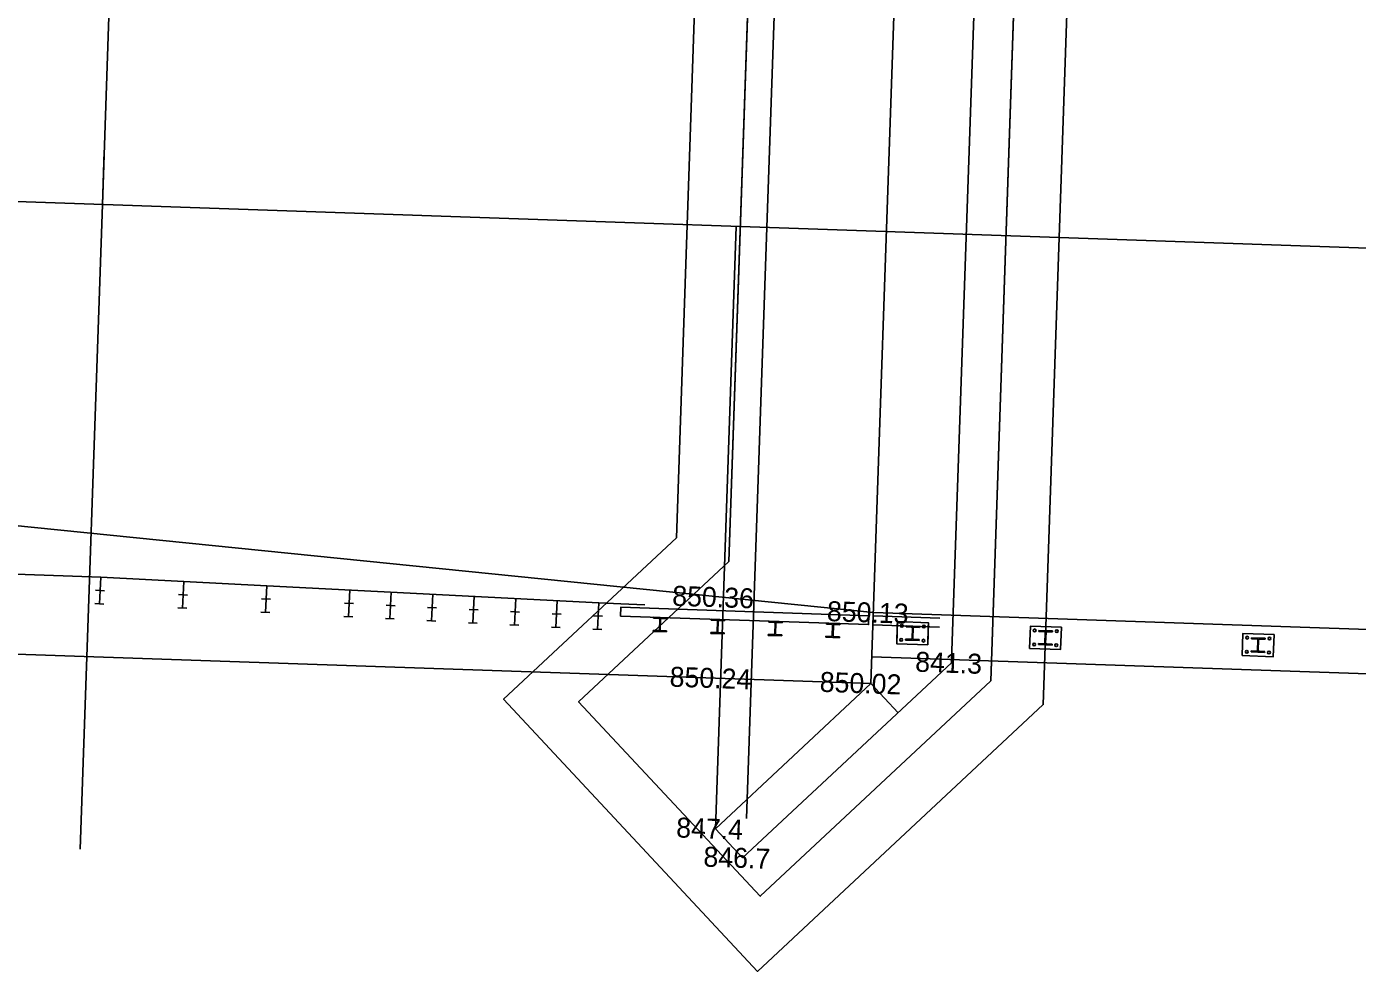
# Model space of a CAD drawing. Extents: x 2191309 to 2193046, y 863659 to 865133.
# Drawn here: x 2191665.3 to 2191715.3, y 865059 to 865094.6 of the extents above; entities that cross this region are included whole.
import ezdxf

# ---------------------------------------------------------------- set-up
doc = ezdxf.new("R2010")
doc.units = 0
for name, color, linetype in [('D_Bridge_Abutment', 7, 'Continuous'), ('D_Bridge_Deck', 7, 'Continuous'), ('D_Bridge_Railing', 7, 'Continuous'), ('D_Bridge_Substructure_Hidden', 7, 'Continuous'), ('D_Guardrail_Beam_Lt', 7, 'Continuous'), ('D_Guardrail_Beam_Rt', 7, 'Continuous'), ('D_Roadway_Centerline', 7, 'Continuous'), ('D_Roadway_Centerline_Text', 7, 'Continuous'), ('D_Roadway_Edge_Shoulder', 7, 'Continuous'), ('D_Roadway_Edge_TW', 7, 'Continuous'), ('H_V CONTROLS', 7, 'Continuous'), ('JUNK', 7, 'Continuous')]:
    doc.layers.add(name, color=color, linetype=linetype)

msp = doc.modelspace()

# ---------------------------------------------------------------- linework, layer by layer
at = {"layer": 'D_Bridge_Abutment'}
for p, q in [((2191697, 865069.864), (2191698.167, 865103.844)), ((2191700.044, 865071.093), (2191700.029, 865070.639)), ((2191700.029, 865070.639), (2191692.176, 865063.308)), ((2191697, 865069.864), (2191691.153, 865064.404)), ((2191698.024, 865068.767), (2191697, 865069.864)), ((2191692.176, 865063.308), (2191691.153, 865064.404))]:
    msp.add_line(p, q, dxfattribs=at)
at = {"layer": 'D_Bridge_Deck'}
for p, q in [((2191697.092, 865072.529), (2191734.07, 865071.26)), ((2191697.035, 865070.863), (2191734.013, 865069.594))]:
    msp.add_line(p, q, dxfattribs=at)
at = {"layer": 'D_Bridge_Railing'}
for p, q in [((2191688.826, 865072.316), (2191688.828, 865072.354)), ((2191689.036, 865072.309), (2191688.826, 865072.316)), ((2191688.828, 865072.354), (2191689.334, 865072.337)), ((2191689.052, 865071.882), (2191689.065, 865072.278)), ((2191689.092, 865072.277), (2191689.078, 865071.881)), ((2191689.333, 865072.299), (2191689.123, 865072.306)), ((2191689.334, 865072.337), (2191689.333, 865072.299)), ((2191690.992, 865072.242), (2191690.993, 865072.28)), ((2191691.202, 865072.235), (2191690.992, 865072.242)), ((2191690.993, 865072.28), (2191691.499, 865072.262)), ((2191691.217, 865071.808), (2191691.231, 865072.204)), ((2191691.257, 865072.203), (2191691.244, 865071.807)), ((2191691.498, 865072.225), (2191691.288, 865072.232)), ((2191691.499, 865072.262), (2191691.498, 865072.225)), ((2191693.157, 865072.168), (2191693.158, 865072.205)), ((2191693.367, 865072.16), (2191693.157, 865072.168)), ((2191693.158, 865072.205), (2191693.665, 865072.188)), ((2191693.663, 865072.15), (2191693.453, 865072.157)), ((2191693.665, 865072.188), (2191693.663, 865072.15)), ((2191688.809, 865071.823), (2191688.811, 865071.861)), ((2191689.316, 865071.805), (2191688.809, 865071.823)), ((2191688.811, 865071.861), (2191689.021, 865071.853)), ((2191689.107, 865071.85), (2191689.317, 865071.843)), ((2191689.317, 865071.843), (2191689.316, 865071.805)), ((2191690.975, 865071.748), (2191690.976, 865071.786)), ((2191691.481, 865071.731), (2191690.975, 865071.748)), ((2191690.976, 865071.786), (2191691.186, 865071.779)), ((2191691.272, 865071.776), (2191691.482, 865071.769)), ((2191691.482, 865071.769), (2191691.481, 865071.731)), ((2191693.14, 865071.674), (2191693.141, 865071.712)), ((2191693.647, 865071.657), (2191693.14, 865071.674)), ((2191693.141, 865071.712), (2191693.352, 865071.705)), ((2191693.382, 865071.734), (2191693.396, 865072.13)), ((2191693.423, 865072.129), (2191693.409, 865071.733)), ((2191693.438, 865071.702), (2191693.648, 865071.695)), ((2191693.648, 865071.695), (2191693.647, 865071.657)), ((2191695.323, 865072.093), (2191695.324, 865072.131)), ((2191695.533, 865072.086), (2191695.323, 865072.093)), ((2191695.324, 865072.131), (2191695.83, 865072.114)), ((2191695.548, 865071.659), (2191695.561, 865072.055)), ((2191695.588, 865072.054), (2191695.574, 865071.658)), ((2191695.829, 865072.076), (2191695.619, 865072.083)), ((2191695.83, 865072.114), (2191695.829, 865072.076)), ((2191698.319, 865071.992), (2191698.32, 865072.028)), ((2191698.53, 865071.985), (2191698.319, 865071.992)), ((2191698.32, 865072.028), (2191698.83, 865072.011)), ((2191698.321, 865071.99), (2191698.322, 865072.028)), ((2191698.531, 865071.983), (2191698.321, 865071.99)), ((2191698.322, 865072.028), (2191698.828, 865072.011)), ((2191698.546, 865071.556), (2191698.56, 865071.953)), ((2191698.546, 865071.556), (2191698.56, 865071.952)), ((2191698.586, 865071.952), (2191698.572, 865071.555)), ((2191698.586, 865071.951), (2191698.573, 865071.555)), ((2191698.827, 865071.973), (2191698.617, 865071.98)), ((2191698.829, 865071.974), (2191698.618, 865071.982)), ((2191698.828, 865072.011), (2191698.827, 865071.973)), ((2191698.83, 865072.011), (2191698.829, 865071.974)), ((2191703.316, 865071.82), (2191703.317, 865071.857)), ((2191703.527, 865071.813), (2191703.316, 865071.82)), ((2191703.317, 865071.857), (2191703.827, 865071.839)), ((2191703.543, 865071.385), (2191703.557, 865071.781)), ((2191703.583, 865071.78), (2191703.569, 865071.384)), ((2191703.826, 865071.803), (2191703.615, 865071.81)), ((2191703.827, 865071.839), (2191703.826, 865071.803)), ((2191695.306, 865071.6), (2191695.307, 865071.638)), ((2191695.812, 865071.582), (2191695.306, 865071.6)), ((2191695.307, 865071.638), (2191695.517, 865071.63)), ((2191695.603, 865071.628), (2191695.813, 865071.62)), ((2191695.813, 865071.62), (2191695.812, 865071.582)), ((2191698.302, 865071.497), (2191698.303, 865071.534)), ((2191698.812, 865071.48), (2191698.302, 865071.497)), ((2191698.303, 865071.534), (2191698.514, 865071.527)), ((2191698.304, 865071.497), (2191698.305, 865071.535)), ((2191698.81, 865071.48), (2191698.304, 865071.497)), ((2191698.305, 865071.535), (2191698.515, 865071.528)), ((2191698.601, 865071.525), (2191698.811, 865071.517)), ((2191698.602, 865071.524), (2191698.813, 865071.516)), ((2191698.811, 865071.517), (2191698.81, 865071.48)), ((2191698.813, 865071.516), (2191698.812, 865071.48)), ((2191703.299, 865071.326), (2191703.3, 865071.362)), ((2191703.809, 865071.308), (2191703.299, 865071.326)), ((2191703.3, 865071.362), (2191703.511, 865071.355)), ((2191703.599, 865071.352), (2191703.81, 865071.345)), ((2191703.81, 865071.345), (2191703.809, 865071.308)), ((2191711.311, 865071.546), (2191711.313, 865071.582)), ((2191711.522, 865071.539), (2191711.311, 865071.546)), ((2191711.313, 865071.582), (2191711.823, 865071.565)), ((2191711.539, 865071.11), (2191711.552, 865071.507)), ((2191711.578, 865071.506), (2191711.565, 865071.109)), ((2191711.821, 865071.528), (2191711.61, 865071.536)), ((2191711.823, 865071.565), (2191711.821, 865071.528)), ((2191711.294, 865071.051), (2191711.296, 865071.088)), ((2191711.804, 865071.034), (2191711.294, 865071.051)), ((2191711.296, 865071.088), (2191711.507, 865071.081)), ((2191711.594, 865071.078), (2191711.806, 865071.07)), ((2191711.806, 865071.07), (2191711.804, 865071.034))]:
    msp.add_line(p, q, dxfattribs=at)
for points in [[(2191687.582, 865072.397), (2191696.91, 865072.077), (2191696.921, 865072.41), (2191687.593, 865072.73), (2191687.582, 865072.397)], [(2191699.58, 865071.985), (2191697.076, 865072.071), (2191697.088, 865072.404), (2191699.592, 865072.318)], [(2191699.158, 865072), (2191699.163, 865072.15), (2191697.997, 865072.191), (2191697.992, 865072.04)], [(2191697.992, 865072.04), (2191697.969, 865071.358), (2191699.135, 865071.318), (2191699.158, 865072)]]:
    msp.add_lwpolyline(points, dxfattribs=at)
for points in [[(2191697.969, 865071.358), (2191699.135, 865071.318), (2191699.163, 865072.15), (2191697.997, 865072.191)], [(2191702.966, 865071.186), (2191704.132, 865071.146), (2191704.16, 865071.979), (2191702.994, 865072.019)], [(2191710.961, 865070.912), (2191712.127, 865070.872), (2191712.156, 865071.705), (2191710.99, 865071.745)]]:
    msp.add_lwpolyline(points, close=True, dxfattribs=at)
for centre in [(2191698.159, 865072.034), (2191698.992, 865072.005), (2191703.156, 865071.862), (2191703.989, 865071.834), (2191698.141, 865071.503), (2191698.141, 865071.503), (2191698.973, 865071.474), (2191698.973, 865071.474), (2191703.138, 865071.331), (2191703.97, 865071.303), (2191711.151, 865071.588), (2191711.984, 865071.559), (2191711.133, 865071.057), (2191711.966, 865071.028)]:
    msp.add_circle(centre, 0.0521, dxfattribs=at)
for centre, radius, start, end in [((2191689.035, 865072.279), 0.0298, 358.0343, 88.0343), ((2191689.122, 865072.276), 0.0298, 88.0343, 178.0343), ((2191691.201, 865072.205), 0.0298, 358.0343, 88.0343), ((2191691.287, 865072.202), 0.0298, 88.0343, 178.0343), ((2191693.366, 865072.131), 0.0298, 358.0343, 88.0343), ((2191693.452, 865072.128), 0.0298, 88.0343, 178.0343), ((2191689.022, 865071.883), 0.0298, 268.0343, 358.0343), ((2191689.108, 865071.88), 0.0298, 178.0343, 268.0343), ((2191691.187, 865071.809), 0.0298, 268.0343, 358.0343), ((2191691.273, 865071.806), 0.0298, 178.0343, 268.0343), ((2191693.353, 865071.735), 0.0298, 268.0343, 358.0343), ((2191693.439, 865071.732), 0.0298, 178.0343, 268.0343), ((2191695.518, 865071.66), 0.0298, 268.0343, 358.0343), ((2191695.532, 865072.056), 0.0298, 358.0343, 88.0343), ((2191695.604, 865071.657), 0.0298, 178.0343, 268.0343), ((2191695.618, 865072.053), 0.0298, 88.0343, 178.0343), ((2191698.529, 865071.954), 0.0308, 358.0343, 88.0343), ((2191698.53, 865071.953), 0.0298, 358.0343, 88.0343), ((2191698.617, 865071.951), 0.0308, 88.0343, 178.0343), ((2191698.616, 865071.95), 0.0298, 88.0343, 178.0343), ((2191703.526, 865071.782), 0.0308, 358.0343, 88.0343), ((2191703.614, 865071.779), 0.0308, 88.0343, 178.0343), ((2191698.515, 865071.557), 0.0308, 268.0343, 358.0343), ((2191698.516, 865071.557), 0.0298, 268.0343, 358.0343), ((2191698.603, 865071.554), 0.0308, 178.0343, 268.0343), ((2191698.602, 865071.554), 0.0298, 178.0343, 268.0343), ((2191703.513, 865071.386), 0.0308, 268.0343, 358.0343), ((2191703.6, 865071.383), 0.0308, 178.0343, 268.0343), ((2191711.521, 865071.508), 0.0308, 358.0343, 88.0343), ((2191711.609, 865071.505), 0.0308, 88.0343, 178.0343), ((2191711.508, 865071.111), 0.0308, 268.0343, 358.0343), ((2191711.595, 865071.108), 0.0308, 178.0343, 268.0343)]:
    msp.add_arc(centre, radius, start, end, dxfattribs=at)
at = {"layer": 'D_Bridge_Substructure_Hidden'}
for p, q in [((2191701.507, 865069.967), (2191702.655, 865103.432)), ((2191700.044, 865071.093), (2191701.131, 865102.741)), ((2191691.654, 865074.449), (2191692.519, 865099.636)), ((2191691.654, 865074.449), (2191686.01, 865069.18)), ((2191701.507, 865069.967), (2191692.835, 865061.87)), ((2191692.835, 865061.87), (2191686.01, 865069.18))]:
    msp.add_line(p, q, dxfattribs=at)
at = {"layer": 'D_Guardrail_Beam_Lt'}
for p, q in [((2191668.04, 865073.86), (2191667.989, 865072.861)), ((2191668.04, 865073.86), (2191674.282, 865073.539)), ((2191671.161, 865073.699), (2191671.109, 865072.7)), ((2191667.848, 865073.369), (2191668.181, 865073.352)), ((2191670.969, 865073.208), (2191671.302, 865073.191)), ((2191674.282, 865073.539), (2191674.23, 865072.54)), ((2191674.282, 865073.539), (2191686.765, 865072.897)), ((2191677.403, 865073.378), (2191677.351, 865072.38)), ((2191678.963, 865073.298), (2191678.912, 865072.3)), ((2191680.523, 865073.218), (2191680.472, 865072.219)), ((2191667.822, 865072.869), (2191668.155, 865072.852)), ((2191670.943, 865072.709), (2191671.276, 865072.692)), ((2191674.09, 865073.048), (2191674.422, 865073.031)), ((2191677.21, 865072.888), (2191677.543, 865072.871)), ((2191678.771, 865072.808), (2191679.104, 865072.79)), ((2191680.331, 865072.727), (2191680.664, 865072.71)), ((2191681.892, 865072.647), (2191682.225, 865072.63)), ((2191682.084, 865073.138), (2191682.033, 865072.139)), ((2191683.644, 865073.058), (2191683.593, 865072.059)), ((2191685.205, 865072.978), (2191685.153, 865071.979)), ((2191686.765, 865072.897), (2191686.714, 865071.899)), ((2191686.765, 865072.897), (2191687.597, 865072.855)), ((2191687.597, 865072.855), (2191688.493, 865072.824)), ((2191674.064, 865072.549), (2191674.397, 865072.532)), ((2191677.185, 865072.388), (2191677.518, 865072.371)), ((2191678.745, 865072.308), (2191679.078, 865072.291)), ((2191680.306, 865072.228), (2191680.639, 865072.211)), ((2191681.866, 865072.148), (2191682.199, 865072.131)), ((2191683.452, 865072.567), (2191683.785, 865072.55)), ((2191685.013, 865072.487), (2191685.346, 865072.47)), ((2191686.573, 865072.407), (2191686.906, 865072.39)), ((2191683.427, 865072.068), (2191683.759, 865072.051)), ((2191684.987, 865071.988), (2191685.32, 865071.97)), ((2191686.547, 865071.907), (2191686.88, 865071.89))]:
    msp.add_line(p, q, dxfattribs=at)
for centre, start, end in [((2191698.159, 865072.034), 358.0343, 178.0343), ((2191698.159, 865072.034), 178.0343, 358.0343), ((2191698.992, 865072.005), 358.0343, 178.0343), ((2191698.992, 865072.005), 178.0343, 358.0343)]:
    msp.add_arc(centre, 0.0521, start, end, dxfattribs=at)
at = {"layer": 'D_Guardrail_Beam_Rt'}
msp.add_line((2191596.207, 865076.325), (2191668.04, 865073.86), dxfattribs=at)
at = {"layer": 'D_Roadway_Centerline'}
msp.add_line((2191489.641, 865093.991), (2191792.637, 865083.591), dxfattribs=at)
at = {"layer": 'D_Roadway_Centerline_Text'}
msp.add_lwpolyline([(2191668.169, 865089.865), (2191668.101, 865087.866)], dxfattribs=at)
at = {"layer": 'D_Roadway_Edge_Shoulder'}
msp.add_line((2191596.104, 865073.327), (2191697, 865069.864), dxfattribs=at)
at = {"layer": 'D_Roadway_Edge_TW'}
msp.add_lwpolyline([(2191517.799, 865081.655), (2191542.797, 865081.16), (2191647.347, 865077.572), (2191697.092, 865072.529)], dxfattribs=at)
at = {"layer": 'H_V CONTROLS'}
msp.add_line((2191691.153, 865064.404), (2191691.93, 865087.048), dxfattribs=at)
msp.add_lwpolyline([(2191687.249, 865105.28), (2191694.559, 865112.104), (2191702.655, 865103.432), (2191701.507, 865069.967), (2191692.835, 865061.87), (2191686.01, 865069.18), (2191691.654, 865074.449), (2191692.519, 865099.636), (2191687.249, 865105.28)], dxfattribs=at)
at = {"layer": 'JUNK'}
for p, q in [((2191693.086, 865087.008), (2191694.067, 865115.576)), ((2191668.101, 865087.866), (2191669.006, 865114.236)), ((2191667.269, 865063.641), (2191668.101, 865087.866)), ((2191692.324, 865064.793), (2191693.086, 865087.008))]:
    msp.add_line(p, q, dxfattribs=at)
msp.add_lwpolyline([(2191684.423, 865105.377), (2191694.656, 865114.931), (2191704.682, 865104.192), (2191703.477, 865069.07), (2191692.738, 865059.043), (2191683.184, 865069.277), (2191689.684, 865075.346), (2191690.492, 865098.876), (2191684.423, 865105.377)], dxfattribs=at)

# ---------------------------------------------------------------- texts
for s, p in [('850.36', (2191689.52, 865072.792)), ('850.13', (2191695.337, 865072.214)), ('841.3', (2191698.656, 865070.311)), ('850.24', (2191689.422, 865069.749)), ('850.02', (2191695.065, 865069.555)), ('847.4', (2191689.669, 865064.08)), ('846.7', (2191690.693, 865062.984))]:
    msp.add_text(s, height=0.75, rotation=358.0343, dxfattribs=at).set_placement(p)

doc.saveas('drawing.dxf')
